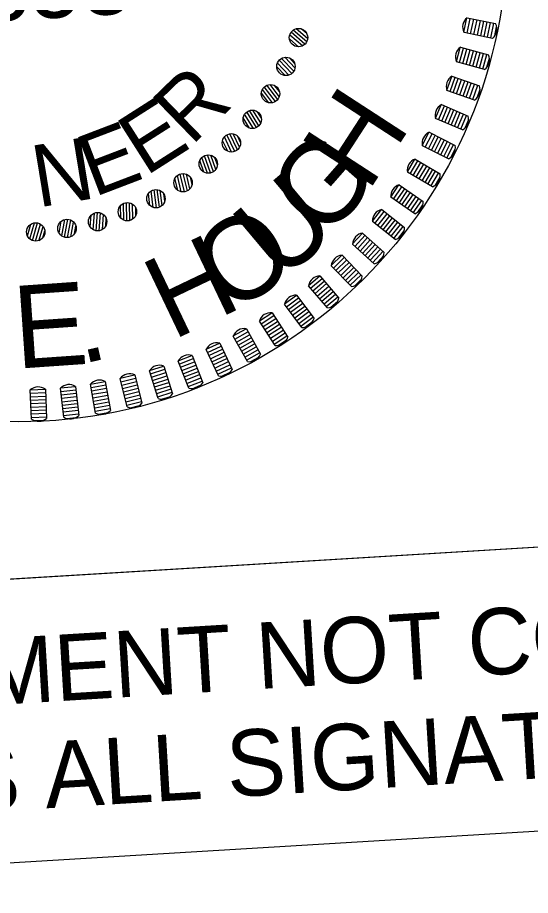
# Model space of a CAD drawing. Extents: x 2110128 to 2112690, y 669500 to 671339.
# Drawn here: x 2112293.6 to 2112336.1, y 670625.1 to 670697.9 of the extents above; entities that cross this region are included whole.
import ezdxf

# ---------------------------------------------------------------- set-up
doc = ezdxf.new("R2010")
doc.units = 0
for name, color, linetype in [('Exist Roads Curbs Text', 7, 'Continuous'), ('Exist Utilities Power Transformer Cogo Comment', 7, 'Continuous'), ('Exist Vegetation Woods Line Text', 7, 'Continuous')]:
    doc.layers.add(name, color=color, linetype=linetype)

msp = doc.modelspace()

# ---------------------------------------------------------------- linework, layer by layer
at = {"layer": 'Exist Roads Curbs Text'}
msp.add_lwpolyline([(2112240.598, 670760.885), (2112340.465, 670766.938), (2112347.271, 670654.644), (2112247.404, 670648.591)], close=True, dxfattribs=at)
at = {"layer": 'Exist Utilities Power Transformer Cogo Comment'}
for p, q in [((2112247.404, 670648.591), (2112447.075, 670660.693)), ((2112448.497, 670637.236), (2112248.826, 670625.134))]:
    msp.add_line(p, q, dxfattribs=at)
at = {"layer": 'Exist Vegetation Woods Line Text'}
for p, q in [((2112330.583, 670696.672), (2112330.83, 670697.866)), ((2112330.845, 670697.878), (2112333.212, 670697.389)), ((2112330.859, 670696.599), (2112331.112, 670697.823)), ((2112331.139, 670696.541), (2112331.392, 670697.766)), ((2112331.418, 670696.484), (2112331.671, 670697.708)), ((2112331.697, 670696.426), (2112331.95, 670697.65)), ((2112331.977, 670696.368), (2112332.23, 670697.592)), ((2112332.256, 670696.31), (2112332.509, 670697.535)), ((2112332.536, 670696.253), (2112332.788, 670697.477)), ((2112332.815, 670696.195), (2112333.068, 670697.419)), ((2112333.144, 670696.376), (2112333.298, 670697.122)), ((2112317.188, 670695.532), (2112316.136, 670696.432)), ((2112317.404, 670695.682), (2112316.25, 670696.669)), ((2112317.553, 670695.889), (2112316.431, 670696.848)), ((2112317.628, 670696.159), (2112316.686, 670696.964)), ((2112317.556, 670696.555), (2112317.088, 670696.955)), ((2112332.959, 670696.165), (2112330.592, 670696.654)), ((2112316.879, 670695.462), (2112316.115, 670696.116)), ((2112329.956, 670694.244), (2112330.281, 670695.419)), ((2112330.227, 670694.153), (2112330.56, 670695.358)), ((2112330.297, 670695.431), (2112332.626, 670694.786)), ((2112330.501, 670694.077), (2112330.835, 670695.282)), ((2112330.776, 670694.001), (2112331.11, 670695.206)), ((2112331.051, 670693.925), (2112331.385, 670695.13)), ((2112331.326, 670693.849), (2112331.66, 670695.054)), ((2112331.601, 670693.773), (2112331.934, 670694.978)), ((2112316.306, 670693.242), (2112315.261, 670694.344)), ((2112316.476, 670693.432), (2112315.46, 670694.503)), ((2112316.579, 670693.693), (2112315.725, 670694.592)), ((2112316.548, 670694.094), (2112316.125, 670694.541)), ((2112332.293, 670693.581), (2112329.964, 670694.226)), ((2112331.876, 670693.697), (2112332.209, 670694.902)), ((2112332.151, 670693.621), (2112332.484, 670694.826)), ((2112332.491, 670693.78), (2112332.694, 670694.514)), ((2112315.76, 670693.079), (2112315.069, 670693.808)), ((2112316.075, 670693.116), (2112315.123, 670694.12)), ((2112329.169, 670691.863), (2112329.571, 670693.014)), ((2112329.433, 670691.755), (2112329.846, 670692.935)), ((2112329.588, 670693.025), (2112331.87, 670692.228)), ((2112329.703, 670691.66), (2112330.115, 670692.841)), ((2112329.972, 670691.566), (2112330.384, 670692.747)), ((2112314.958, 670690.93), (2112314.034, 670692.135)), ((2112315.147, 670691.101), (2112314.249, 670692.273)), ((2112315.277, 670691.35), (2112314.522, 670692.334)), ((2112315.288, 670691.752), (2112314.914, 670692.241)), ((2112330.241, 670691.472), (2112330.654, 670692.653)), ((2112330.511, 670691.378), (2112330.923, 670692.558)), ((2112330.78, 670691.284), (2112331.192, 670692.464)), ((2112331.049, 670691.19), (2112331.461, 670692.37)), ((2112331.318, 670691.096), (2112331.731, 670692.276)), ((2112314.399, 670690.825), (2112313.787, 670691.622)), ((2112314.716, 670690.829), (2112313.873, 670691.927)), ((2112331.458, 670691.048), (2112329.176, 670691.844)), ((2112331.668, 670691.233), (2112331.919, 670691.952)), ((2112328.227, 670689.539), (2112328.704, 670690.661)), ((2112328.483, 670689.414), (2112328.973, 670690.564)), ((2112328.722, 670690.671), (2112330.946, 670689.725)), ((2112313.125, 670688.696), (2112312.402, 670689.877)), ((2112313.377, 670688.772), (2112312.583, 670690.067)), ((2112313.582, 670688.923), (2112312.811, 670690.182)), ((2112313.737, 670689.156), (2112313.09, 670690.214)), ((2112313.791, 670689.555), (2112313.469, 670690.08)), ((2112328.746, 670689.302), (2112329.235, 670690.452)), ((2112329.008, 670689.19), (2112329.498, 670690.341)), ((2112329.271, 670689.079), (2112329.76, 670690.229)), ((2112329.533, 670688.967), (2112330.023, 670690.117)), ((2112329.796, 670688.855), (2112330.285, 670690.006)), ((2112330.058, 670688.744), (2112330.548, 670689.894)), ((2112312.809, 670688.725), (2112312.284, 670689.583)), ((2112330.456, 670688.574), (2112328.232, 670689.52)), ((2112330.321, 670688.632), (2112330.81, 670689.782)), ((2112330.679, 670688.745), (2112330.977, 670689.446)), ((2112327.133, 670687.283), (2112327.684, 670688.371)), ((2112327.702, 670688.379), (2112329.858, 670687.288)), ((2112311.009, 670686.804), (2112310.576, 670687.711)), ((2112311.32, 670686.742), (2112310.724, 670687.992)), ((2112311.578, 670686.791), (2112310.925, 670688.162)), ((2112311.798, 670686.919), (2112311.163, 670688.252)), ((2112311.977, 670687.135), (2112311.443, 670688.255)), ((2112312.072, 670687.526), (2112311.807, 670688.082)), ((2112327.381, 670687.14), (2112327.945, 670688.256)), ((2112327.635, 670687.012), (2112328.2, 670688.127)), ((2112327.89, 670686.883), (2112328.454, 670687.998)), ((2112328.144, 670686.754), (2112328.709, 670687.87)), ((2112328.399, 670686.625), (2112328.963, 670687.741)), ((2112329.294, 670686.173), (2112327.138, 670687.264)), ((2112328.654, 670686.497), (2112329.218, 670687.612)), ((2112328.908, 670686.368), (2112329.472, 670687.483)), ((2112329.163, 670686.239), (2112329.727, 670687.355)), ((2112329.527, 670686.328), (2112329.871, 670687.008)), ((2112309.32, 670684.987), (2112308.858, 670686.292)), ((2112309.582, 670685.008), (2112309.076, 670686.44)), ((2112309.815, 670685.113), (2112309.322, 670686.505)), ((2112310.015, 670685.309), (2112309.601, 670686.478)), ((2112310.15, 670685.689), (2112309.945, 670686.269)), ((2112309.017, 670685.081), (2112308.682, 670686.029)), ((2112325.893, 670685.104), (2112326.514, 670686.153)), ((2112326.13, 670684.945), (2112326.767, 670686.021)), ((2112326.376, 670684.8), (2112327.013, 670685.876)), ((2112326.533, 670686.16), (2112328.612, 670684.929)), ((2112326.621, 670684.655), (2112327.258, 670685.73)), ((2112326.867, 670684.509), (2112327.504, 670685.585)), ((2112307.148, 670683.451), (2112306.825, 670684.797)), ((2112307.411, 670683.445), (2112307.057, 670684.921)), ((2112307.653, 670683.524), (2112307.309, 670684.96)), ((2112307.872, 670683.699), (2112307.583, 670684.904)), ((2112327.976, 670683.853), (2112325.896, 670685.084)), ((2112327.112, 670684.364), (2112327.749, 670685.44)), ((2112327.358, 670684.219), (2112327.995, 670685.294)), ((2112327.603, 670684.073), (2112328.24, 670685.149)), ((2112327.849, 670683.928), (2112328.486, 670685.004)), ((2112306.857, 670683.576), (2112306.622, 670684.553)), ((2112308.047, 670684.062), (2112307.903, 670684.66)), ((2112324.511, 670683.011), (2112325.2, 670684.017)), ((2112325.219, 670684.023), (2112327.213, 670682.657)), ((2112328.219, 670683.993), (2112328.607, 670684.648)), ((2112304.551, 670682.305), (2112304.42, 670683.301)), ((2112304.827, 670682.15), (2112304.647, 670683.522)), ((2112305.088, 670682.116), (2112304.89, 670683.622)), ((2112305.337, 670682.17), (2112305.145, 670683.634)), ((2112305.574, 670682.321), (2112305.412, 670683.55)), ((2112324.738, 670682.837), (2112325.444, 670683.869)), ((2112324.973, 670682.676), (2112325.68, 670683.707)), ((2112325.208, 670682.515), (2112325.915, 670683.546)), ((2112325.444, 670682.354), (2112326.15, 670683.385)), ((2112302.639, 670681.038), (2112302.6, 670682.556)), ((2112305.785, 670682.663), (2112305.705, 670683.273)), ((2112326.507, 670681.626), (2112324.513, 670682.992)), ((2112325.679, 670682.193), (2112326.386, 670683.224)), ((2112325.914, 670682.031), (2112326.621, 670683.063)), ((2112326.15, 670681.87), (2112326.856, 670682.901)), ((2112326.385, 670681.709), (2112327.092, 670682.74)), ((2112302.124, 670681.281), (2112302.098, 670682.286)), ((2112302.383, 670681.098), (2112302.348, 670682.482)), ((2112302.892, 670681.066), (2112302.854, 670682.542)), ((2112303.143, 670681.19), (2112303.111, 670682.43)), ((2112303.389, 670681.509), (2112303.373, 670682.124)), ((2112322.994, 670681.015), (2112323.748, 670681.973)), ((2112323.767, 670681.977), (2112325.667, 670680.483)), ((2112326.758, 670681.749), (2112327.189, 670682.377)), ((2112297.234, 670679.788), (2112297.486, 670681.15)), ((2112297.471, 670679.676), (2112297.748, 670681.169)), ((2112297.725, 670679.65), (2112297.994, 670681.102)), ((2112299.604, 670680.518), (2112299.684, 670681.52)), ((2112299.843, 670680.308), (2112299.952, 670681.689)), ((2112300.091, 670680.222), (2112300.21, 670681.736)), ((2112300.346, 670680.223), (2112300.462, 670681.695)), ((2112300.608, 670680.32), (2112300.706, 670681.557)), ((2112300.886, 670680.612), (2112300.935, 670681.225)), ((2112323.209, 670680.826), (2112323.982, 670681.809)), ((2112323.433, 670680.65), (2112324.206, 670681.632)), ((2112323.657, 670680.473), (2112324.43, 670681.456)), ((2112323.881, 670680.297), (2112324.654, 670681.279)), ((2112324.105, 670680.121), (2112324.878, 670681.103)), ((2112294.395, 670679.798), (2112294.681, 670680.762)), ((2112294.584, 670679.544), (2112294.978, 670680.871)), ((2112294.809, 670679.407), (2112295.241, 670680.863)), ((2112295.058, 670679.355), (2112295.478, 670680.771)), ((2112295.336, 670679.396), (2112295.688, 670680.585)), ((2112297.018, 670680.021), (2112297.202, 670681.01)), ((2112297.996, 670679.72), (2112298.223, 670680.939)), ((2112298.303, 670679.981), (2112298.415, 670680.586)), ((2112324.894, 670679.5), (2112322.994, 670680.995)), ((2112324.33, 670679.944), (2112325.103, 670680.927)), ((2112324.554, 670679.768), (2112325.327, 670680.75)), ((2112324.778, 670679.591), (2112325.551, 670680.574)), ((2112295.668, 670679.624), (2112295.843, 670680.214)), ((2112321.349, 670679.123), (2112322.164, 670680.029)), ((2112321.55, 670678.921), (2112322.386, 670679.85)), ((2112321.762, 670678.73), (2112322.598, 670679.659)), ((2112322.184, 670680.032), (2112323.98, 670678.415)), ((2112325.153, 670679.607), (2112325.624, 670680.205)), ((2112323.144, 670677.486), (2112321.347, 670679.103)), ((2112321.974, 670678.539), (2112322.811, 670679.468)), ((2112322.186, 670678.348), (2112323.023, 670679.277)), ((2112322.398, 670678.157), (2112323.235, 670679.086)), ((2112319.581, 670677.344), (2112320.455, 670678.194)), ((2112320.475, 670678.196), (2112322.16, 670676.464)), ((2112322.61, 670677.966), (2112323.447, 670678.895)), ((2112322.822, 670677.775), (2112323.659, 670678.705)), ((2112323.034, 670677.585), (2112323.871, 670678.514)), ((2112319.769, 670677.129), (2112320.665, 670678)), ((2112319.968, 670676.924), (2112320.864, 670677.796)), ((2112320.167, 670676.72), (2112321.063, 670677.592)), ((2112323.41, 670677.575), (2112323.919, 670678.141)), ((2112321.265, 670675.592), (2112319.579, 670677.324)), ((2112320.366, 670676.515), (2112321.262, 670677.387)), ((2112320.565, 670676.311), (2112321.461, 670677.183)), ((2112320.764, 670676.106), (2112321.66, 670676.978)), ((2112320.963, 670675.902), (2112321.859, 670676.774)), ((2112317.701, 670675.685), (2112318.629, 670676.476)), ((2112317.874, 670675.458), (2112318.825, 670676.269)), ((2112318.059, 670675.241), (2112319.01, 670676.052)), ((2112318.648, 670676.477), (2112320.216, 670674.637)), ((2112321.162, 670675.698), (2112322.058, 670676.569)), ((2112321.536, 670675.664), (2112322.082, 670676.195)), ((2112319.264, 670673.826), (2112317.697, 670675.666)), ((2112318.244, 670675.024), (2112319.195, 670675.835)), ((2112318.429, 670674.807), (2112319.38, 670675.618)), ((2112318.614, 670674.59), (2112319.565, 670675.4)), ((2112315.714, 670674.155), (2112316.692, 670674.883)), ((2112315.872, 670673.917), (2112316.875, 670674.663)), ((2112316.712, 670674.882), (2112318.155, 670672.943)), ((2112318.799, 670674.373), (2112319.75, 670675.183)), ((2112318.984, 670674.155), (2112319.935, 670674.966)), ((2112319.169, 670673.938), (2112320.12, 670674.749)), ((2112317.152, 670672.197), (2112315.709, 670674.136)), ((2112316.042, 670673.688), (2112317.045, 670674.434)), ((2112316.213, 670673.459), (2112317.216, 670674.205)), ((2112316.383, 670673.23), (2112317.386, 670673.976)), ((2112319.54, 670673.88), (2112320.119, 670674.373)), ((2112313.631, 670672.759), (2112314.655, 670673.421)), ((2112313.773, 670672.511), (2112314.823, 670673.189)), ((2112314.675, 670673.418), (2112315.986, 670671.388)), ((2112316.553, 670673.001), (2112317.556, 670673.747)), ((2112316.723, 670672.772), (2112317.726, 670673.519)), ((2112316.894, 670672.544), (2112317.897, 670673.29)), ((2112314.936, 670670.71), (2112313.625, 670672.74)), ((2112313.928, 670672.272), (2112314.978, 670672.95)), ((2112314.082, 670672.032), (2112315.133, 670672.71)), ((2112314.237, 670671.792), (2112315.287, 670672.47)), ((2112317.064, 670672.315), (2112318.067, 670673.061)), ((2112317.43, 670672.232), (2112318.041, 670672.686)), ((2112311.46, 670671.504), (2112312.526, 670672.096)), ((2112311.585, 670671.247), (2112312.678, 670671.854)), ((2112312.546, 670672.093), (2112313.72, 670669.98)), ((2112314.392, 670671.553), (2112315.442, 670672.231)), ((2112314.547, 670671.313), (2112315.597, 670671.991)), ((2112314.701, 670671.073), (2112315.752, 670671.751)), ((2112309.211, 670670.395), (2112310.314, 670670.916)), ((2112310.333, 670670.911), (2112311.365, 670668.726)), ((2112312.627, 670669.373), (2112311.453, 670671.486)), ((2112311.724, 670670.998), (2112312.817, 670671.605)), ((2112311.863, 670670.749), (2112312.955, 670671.356)), ((2112312.001, 670670.499), (2112313.094, 670671.106)), ((2112314.856, 670670.834), (2112315.906, 670671.512)), ((2112315.216, 670670.727), (2112315.856, 670671.14)), ((2112310.234, 670668.192), (2112309.203, 670670.377)), ((2112309.319, 670670.131), (2112310.45, 670670.664)), ((2112309.441, 670669.873), (2112310.571, 670670.406)), ((2112312.14, 670670.25), (2112313.232, 670670.857)), ((2112312.278, 670670.001), (2112313.371, 670670.608)), ((2112312.417, 670669.751), (2112313.509, 670670.358)), ((2112306.894, 670669.437), (2112308.028, 670669.884)), ((2112306.984, 670669.166), (2112308.147, 670669.624)), ((2112308.047, 670669.878), (2112308.933, 670667.629)), ((2112309.563, 670669.615), (2112310.693, 670670.148)), ((2112309.685, 670669.357), (2112310.815, 670669.891)), ((2112309.806, 670669.099), (2112310.937, 670669.633)), ((2112312.555, 670669.502), (2112313.648, 670670.109)), ((2112312.907, 670669.371), (2112313.573, 670669.741)), ((2112304.518, 670668.635), (2112305.68, 670669.005)), ((2112304.59, 670668.358), (2112305.781, 670668.738)), ((2112305.698, 670668.998), (2112306.433, 670666.696)), ((2112307.769, 670667.171), (2112306.884, 670669.42)), ((2112307.089, 670668.901), (2112308.252, 670669.359)), ((2112307.193, 670668.635), (2112308.356, 670669.093)), ((2112307.297, 670668.37), (2112308.461, 670668.828)), ((2112309.928, 670668.841), (2112311.059, 670669.375)), ((2112310.05, 670668.583), (2112311.18, 670669.117)), ((2112310.172, 670668.325), (2112311.302, 670668.859)), ((2112302.095, 670667.991), (2112303.278, 670668.284)), ((2112302.148, 670667.71), (2112303.362, 670668.011)), ((2112303.296, 670668.276), (2112303.877, 670665.93)), ((2112305.242, 670666.316), (2112304.507, 670668.618)), ((2112304.677, 670668.087), (2112305.868, 670668.467)), ((2112304.764, 670667.815), (2112305.955, 670668.195)), ((2112307.402, 670668.105), (2112308.565, 670668.562)), ((2112307.506, 670667.839), (2112308.67, 670668.297)), ((2112307.611, 670667.574), (2112308.774, 670668.032)), ((2112310.514, 670668.171), (2112311.203, 670668.496)), ((2112297.147, 670667.19), (2112298.359, 670667.325)), ((2112298.376, 670667.314), (2112298.642, 670664.912)), ((2112300.046, 670665.115), (2112299.621, 670667.494)), ((2112299.634, 670667.509), (2112300.834, 670667.723)), ((2112299.669, 670667.225), (2112300.9, 670667.445)), ((2112300.852, 670667.713), (2112301.276, 670665.334)), ((2112302.664, 670665.629), (2112302.083, 670667.975)), ((2112302.217, 670667.434), (2112303.43, 670667.734)), ((2112302.286, 670667.157), (2112303.499, 670667.457)), ((2112304.85, 670667.543), (2112306.041, 670667.923)), ((2112304.937, 670667.271), (2112306.128, 670667.651)), ((2112305.024, 670667), (2112306.215, 670667.38)), ((2112307.715, 670667.308), (2112308.879, 670667.766)), ((2112308.047, 670667.132), (2112308.756, 670667.411)), ((2112294.736, 670664.609), (2112294.629, 670667.024)), ((2112294.641, 670666.751), (2112295.89, 670666.806)), ((2112294.644, 670667.037), (2112295.862, 670667.091)), ((2112295.878, 670667.079), (2112295.985, 670664.665)), ((2112297.399, 670664.774), (2112297.133, 670667.176)), ((2112297.163, 670666.905), (2112298.406, 670667.043)), ((2112297.195, 670666.622), (2112298.437, 670666.759)), ((2112299.719, 670666.944), (2112300.95, 670667.164)), ((2112299.769, 670666.664), (2112301, 670666.883)), ((2112299.819, 670666.383), (2112301.05, 670666.602)), ((2112302.354, 670666.88), (2112303.568, 670667.18)), ((2112302.423, 670666.603), (2112303.636, 670666.903)), ((2112302.491, 670666.326), (2112303.705, 670666.626)), ((2112305.111, 670666.728), (2112306.301, 670667.108)), ((2112305.197, 670666.456), (2112306.388, 670666.836)), ((2112294.654, 670666.466), (2112295.903, 670666.522)), ((2112294.667, 670666.181), (2112295.916, 670666.237)), ((2112294.679, 670665.896), (2112295.928, 670665.952)), ((2112297.226, 670666.338), (2112298.468, 670666.476)), ((2112297.257, 670666.055), (2112298.5, 670666.192)), ((2112297.289, 670665.771), (2112298.531, 670665.909)), ((2112299.869, 670666.102), (2112301.1, 670666.322)), ((2112299.92, 670665.821), (2112301.15, 670666.041)), ((2112302.56, 670666.049), (2112303.773, 670666.349)), ((2112302.628, 670665.772), (2112303.842, 670666.073)), ((2112305.517, 670666.259), (2112306.242, 670666.49)), ((2112294.692, 670665.611), (2112295.941, 670665.667)), ((2112294.704, 670665.326), (2112295.953, 670665.382)), ((2112294.717, 670665.041), (2112295.966, 670665.097)), ((2112297.32, 670665.488), (2112298.563, 670665.625)), ((2112297.352, 670665.204), (2112298.594, 670665.342)), ((2112299.97, 670665.54), (2112301.2, 670665.76)), ((2112300.02, 670665.26), (2112301.25, 670665.479)), ((2112300.31, 670665.022), (2112301.06, 670665.155)), ((2112302.934, 670665.554), (2112303.673, 670665.737)), ((2112294.73, 670664.756), (2112295.979, 670664.812)), ((2112294.986, 670664.482), (2112295.747, 670664.516)), ((2112297.383, 670664.92), (2112298.626, 670665.058)), ((2112297.657, 670664.664), (2112298.414, 670664.748))]:
    msp.add_line(p, q, dxfattribs=at)
for centre, radius in [((2112293.63, 670704.945), 40.556), ((2112316.869, 670696.225), 0.762), ((2112315.83, 670693.838), 0.762), ((2112314.548, 670691.572), 0.762), ((2112313.035, 670689.453), 0.762), ((2112311.31, 670687.504), 0.762), ((2112309.39, 670685.746), 0.762), ((2112307.297, 670684.198), 0.762), ((2112305.053, 670682.878), 0.762), ((2112302.684, 670681.799), 0.762), ((2112297.674, 670680.411), 0.762), ((2112300.215, 670680.973), 0.762), ((2112295.087, 670680.117), 0.762)]:
    msp.add_circle(centre, radius, dxfattribs=at)
for centre, radius, start, end in [((2112331.461, 670697.113), 0.983, 128.82789, 207.82138), ((2112332.281, 670696.943), 1.032, 311.05415, 25.59512), ((2112330.861, 670694.626), 0.983, 125.03842, 204.03191), ((2112331.668, 670694.403), 1.032, 307.26468, 21.80565), ((2112330.098, 670692.184), 0.983, 121.24894, 200.24243), ((2112330.888, 670691.908), 1.032, 303.4752, 18.01617), ((2112329.175, 670689.799), 0.983, 117.45947, 196.45296), ((2112329.945, 670689.471), 1.032, 299.68573, 14.2267), ((2112328.096, 670687.479), 0.983, 113.67, 192.66349), ((2112328.843, 670687.101), 1.032, 295.89626, 10.43723), ((2112326.867, 670685.236), 0.983, 109.88052, 188.87401), ((2112327.587, 670684.809), 1.032, 292.10678, 6.64775), ((2112325.492, 670683.079), 0.983, 106.09105, 185.08454), ((2112326.182, 670682.606), 1.032, 288.31731, 2.85828), ((2112323.977, 670681.017), 0.983, 102.30157, 181.29507), ((2112324.635, 670680.499), 1.032, 284.52784, 359.0688), ((2112322.329, 670679.06), 0.983, 98.5121, 177.50559), ((2112320.556, 670677.216), 0.983, 94.72263, 173.71612), ((2112322.951, 670678.5), 1.032, 280.73836, 355.27933), ((2112318.664, 670675.494), 0.983, 90.93315, 169.92665), ((2112321.14, 670676.617), 1.032, 276.94889, 351.48986), ((2112316.663, 670673.9), 0.983, 87.14368, 166.13717), ((2112319.207, 670674.857), 1.032, 273.15942, 347.70038), ((2112314.561, 670672.442), 0.983, 83.35421, 162.3477), ((2112317.163, 670673.229), 1.032, 269.36994, 343.91091), ((2112312.368, 670671.126), 0.983, 79.56473, 158.55822), ((2112310.092, 670669.958), 0.983, 75.77526, 154.76875), ((2112315.016, 670671.739), 1.032, 265.58047, 340.12144), ((2112307.744, 670668.943), 0.983, 71.98578, 150.97928), ((2112312.774, 670670.395), 1.032, 261.79099, 336.33196), ((2112305.333, 670668.086), 0.983, 68.19631, 147.1898), ((2112302.872, 670667.389), 0.983, 64.40684, 143.40033), ((2112310.449, 670669.201), 1.032, 258.00152, 332.54249), ((2112295.287, 670666.294), 0.983, 53.03842, 132.03191), ((2112297.838, 670666.491), 0.983, 56.82789, 135.82138), ((2112300.37, 670666.857), 0.983, 60.61736, 139.61086), ((2112308.05, 670668.164), 1.032, 254.21205, 328.75302), ((2112305.588, 670667.288), 1.032, 250.42257, 324.96354), ((2112303.073, 670666.577), 1.032, 246.6331, 321.17407), ((2112300.517, 670666.033), 1.032, 242.84363, 317.38459), ((2112295.324, 670665.457), 1.032, 235.26468, 309.80565), ((2112297.93, 670665.659), 1.032, 239.05415, 313.59512)]:
    msp.add_arc(centre, radius, start, end, dxfattribs=at)

# ---------------------------------------------------------------- texts
at = {"layer": 'Exist Utilities Power Transformer Cogo Comment'}
for s, p in [('DOCUMENT NOT CONSIDERED FINAL', (2112269.062, 670639.54)), ('UNLESS ALL SIGNATURES COMPLETED', (2112264.533, 670630.449))]:
    msp.add_text(s, height=5.5, rotation=3.46824, dxfattribs=at).set_placement(p)
at = {"layer": 'Exist Vegetation Woods Line Text'}
for s, height, rotation, p in [('036853', 5.7051, 3.48253, (2112277.746, 670696.719)), ('R', 5.135, 44.12769, (2112307.986, 670687.189)), ('H', 6.846, 57.00299, (2112322.615, 670683.339)), ('E', 5.135, 32.51479, (2112304.195, 670684.701)), ('E', 5.135, 20.90189, (2112299.903, 670682.978)), ('N', 5.135, 9.28898, (2112295.262, 670682.139)), ('G', 6.846, 48.71691, (2112319.052, 670679.32)), ('U', 6.846, 40.01653, (2112315.302, 670675.905)), ('O', 6.846, 32.55906, (2112311.1, 670673.203)), ('H', 6.846, 25.5159, (2112306.406, 670671.1)), ('E', 6.846, 3.9721, (2112293.473, 670668.78)), ('.', 6.846, 12.67248, (2112298.817, 670669.152))]:
    msp.add_text(s, height=height, rotation=rotation, dxfattribs=at).set_placement(p)

doc.saveas('drawing.dxf')
